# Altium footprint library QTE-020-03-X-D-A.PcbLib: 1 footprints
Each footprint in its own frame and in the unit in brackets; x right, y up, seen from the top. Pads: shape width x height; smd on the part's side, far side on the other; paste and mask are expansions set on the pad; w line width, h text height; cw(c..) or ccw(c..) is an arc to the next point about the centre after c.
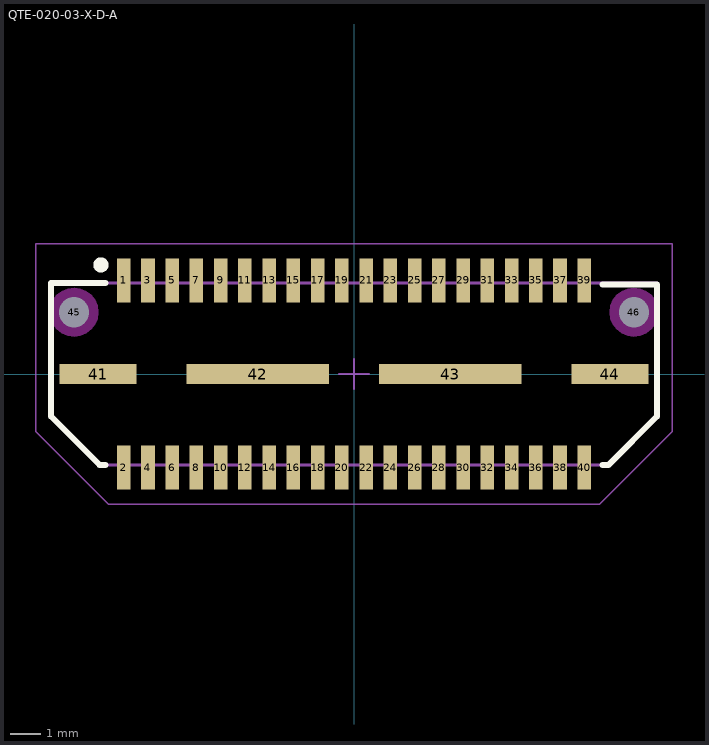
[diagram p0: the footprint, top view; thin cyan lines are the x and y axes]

## QTE-020-03-X-D-A [mm] "0.80mm pitch, 40 pin, high speed terminal strip"
height 4.27
pads (46):
  rect 0.45x1.45 smd mask+0: 1(-7.6,3.09) 2(-7.6,-3.09) 3(-6.8,3.09) 4(-6.8,-3.09) 5(-6,3.09) 6(-6,-3.09) 7(-5.2,3.09) 8(-5.2,-3.09) 9(-4.4,3.09) 10(-4.4,-3.09) 11(-3.6,3.09) 12(-3.6,-3.09) 13(-2.8,3.09) 14(-2.8,-3.09) 15(-2,3.09) 16(-2,-3.09) 17(-1.2,3.09) 18(-1.2,-3.09) 19(-0.4,3.09) 20(-0.4,-3.09) 21(0.4,3.09) 22(0.4,-3.09) 23(1.2,3.09) 24(1.2,-3.09) 25(2,3.09) 26(2,-3.09) 27(2.8,3.09) 28(2.8,-3.09) 29(3.6,3.09) 30(3.6,-3.09) 31(4.4,3.09) 32(4.4,-3.09) 33(5.2,3.09) 34(5.2,-3.09) 35(6,3.09) 36(6,-3.09) 37(6.8,3.09) 38(6.8,-3.09) 39(7.6,3.09) 40(7.6,-3.09)
  rect 2.55x0.65 smd mask+0: 41(-8.445,0) 44(8.445,0)
  rect 4.7x0.65 smd mask+0: 42(-3.175,0) 43(3.175,0)
  round 0.5 hole 1 unplated mask+0: 45(-9.24,2.04) 46(9.24,2.04)
Top Overlay:
  circle w0.25: c-8.35,3.6 r0.125
  lines w0.2: -8.2,-3 -8.4,-3 -10,-1.4 -10,3 -8.2,3 ; 8.2,-3 8.4,-3 10,-1.4 10,2.95 8.2,2.95
Keep-Out Layer:
  pour cut-out: 10.047,2.04 10.019,2.249 9.939,2.443 9.811,2.611 9.643,2.739 9.449,2.819 9.24,2.847 9.031,2.819 8.837,2.739 8.669,2.611 8.541,2.443 8.461,2.249 8.433,2.04 8.461,1.831 8.541,1.637 8.669,1.469 8.837,1.341 9.031,1.261 9.24,1.233 9.449,1.261 9.643,1.341 9.811,1.469 9.939,1.637 10.019,1.831
  pour cut-out: -8.433,2.04 -8.461,2.249 -8.541,2.443 -8.669,2.611 -8.837,2.739 -9.031,2.819 -9.24,2.847 -9.449,2.819 -9.643,2.739 -9.811,2.611 -9.939,2.443 -10.019,2.249 -10.047,2.04 -10.019,1.831 -9.939,1.637 -9.811,1.469 -9.643,1.341 -9.449,1.261 -9.24,1.233 -9.031,1.261 -8.837,1.341 -8.669,1.469 -8.541,1.637 -8.461,1.831
Mechanical 13:
  lines w0.01: -10,-1.4 -10,3 10,3 10,-1.4 8.4,-3 -8.4,-3 -10,-1.4
  lines w0.1: -10,-1.4 -10,3 10,3 10,-1.4 8.4,-3 -8.4,-3 -10,-1.4
  text ".Designator" at 0.254,0.254 h1.52
Mechanical 15:
  lines w0.05: -0.5,0 0.5,0 ; 0,-0.5 0,0.5 ; -10.5,-1.9 -10.5,4.3 10.5,4.3 10.5,-1.9 8.1,-4.3 -8.1,-4.3 -10.5,-1.9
